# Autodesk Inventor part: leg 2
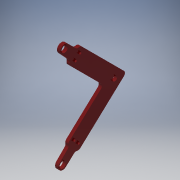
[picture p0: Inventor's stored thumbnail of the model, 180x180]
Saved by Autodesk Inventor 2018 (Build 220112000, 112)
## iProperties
Created: 2023-12
Part Number: leg 2
Material: Generic
Document SubType Name: Modeling
Designer: DDUGKY
Density: 1 g/cm^3
Appearance: Default
Author: DDUGKY
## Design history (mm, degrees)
sketch "Sketch1"
  geometry: L1 (146.034, 101.302)-(246.034, 101.302); L2 (146.034, 101.302)-(-4.296, -38.075); L3 (-38.29, -1.409)-(73.961, 102.664); L4 (-44.094, -61.337)-(-11.095, -30.742); L5 (-11.095, -30.742)-(-4.296, -38.075); L6 (-38.29, -1.409)-(-31.492, -8.742); L7 (-31.492, -8.742)-(-63.334, -40.585); L8 (-37.814, 271.008)-(-5.994, 239.188); L9 (-27.208, 217.975)-(-57.824, 250.998); L10 (-5.994, 239.188)-(1.077, 246.259); L11 (-34.279, 210.904)-(-27.208, 217.975); L12 (146.034, 101.302)-(1.077, 246.259); L13 (73.961, 102.664)-(-34.279, 210.904); C1 r 7.5 at (109.997, 101.983); C2 r 10 at (-53.714, -50.961); C3 r 3.75 at (-16.514, -2.834); C4 r 3.75 at (-2.916, -17.501); C5 r 10 at (-47.819, 261.003); C6 r 3.75 at (-12.464, 211.505); C7 r 3.75 at (1.678, 225.647); A1 r 14.149 centre (-53.714, -50.961) between (-63.334, -40.585) and (-44.094, -61.337); A2 r 14.149 centre (-47.819, 261.003) between (-37.814, 271.008) and (-57.824, 250.998)
  constraints: 26 end point, 9 centre point, 4 point on circle, 2 coincident, 2 parallel, 1 horizontal, 1 perpendicular, 1 tangent
  dimensions: "d7" = 50 distance between parallel lines of L2 L3; "d9" = 15 diameter of C1; "d13" = 45 distance of L4.start L4.end; "d14" = 10 distance of L3.start L6.end; "d15" = 20 diameter of C2; "d19" = 7.5 diameter of C3; "d20" = 7.5 diameter of C4; "d24" = 20 diameter of C5
extrude "Extrusion3" new body sketch "Sketch1" stored distance "d21" = 10; taper "d22" = 0 deg
fillet "Fillet1" dims "d23" = 10
body "Solid3"
